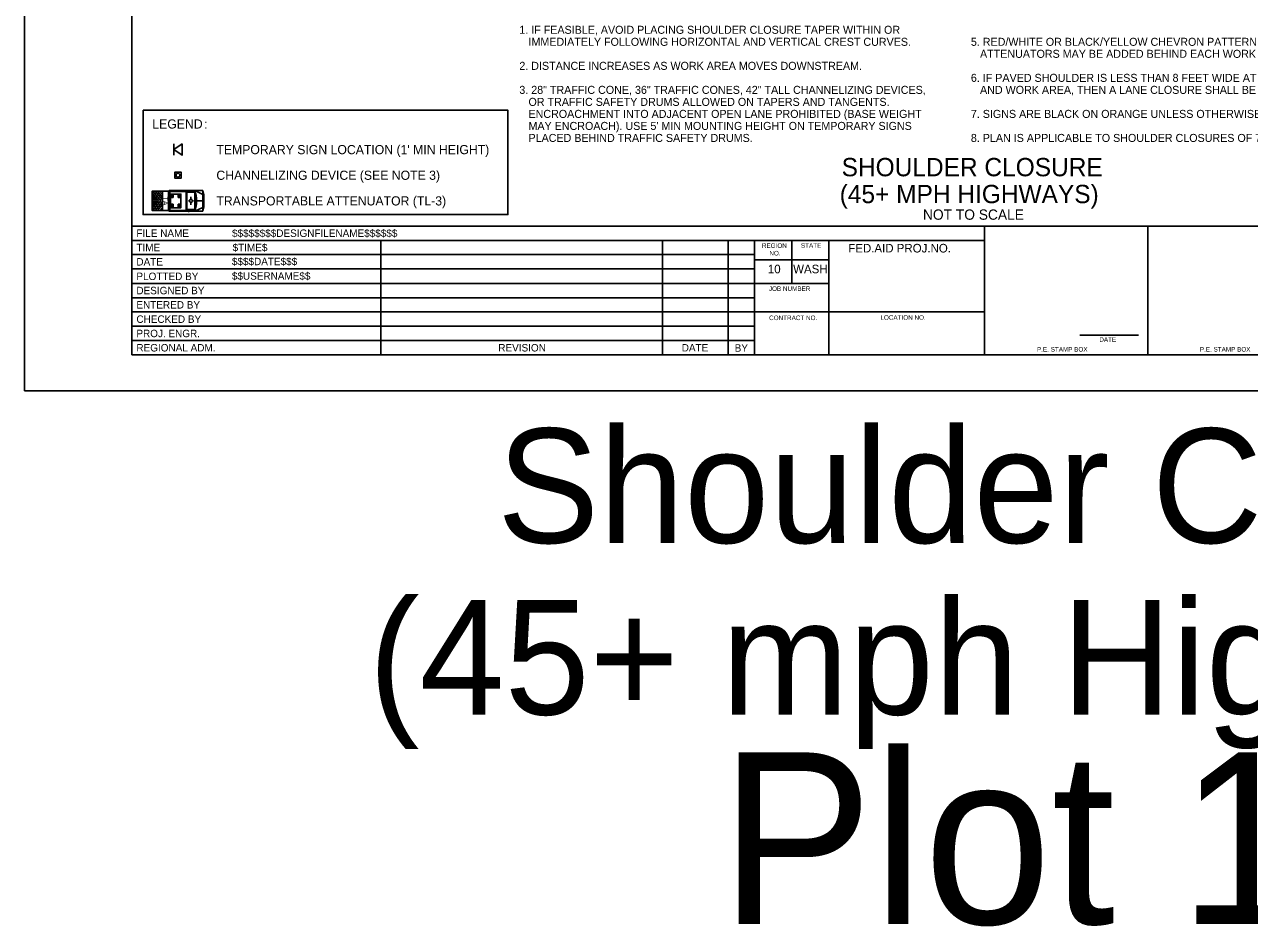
# Model space of a CAD drawing. Extents: x 99999.1 to 100055.7, y 99995 to 100013.2.
# Drawn here: x 99999.06 to 100009.77, y 99995.01 to 100002.89 of the extents above; entities that cross this region are included whole.
import ezdxf

# ---------------------------------------------------------------- set-up
doc = ezdxf.new("R2010")
doc.units = 0
for name, color, linetype in [('SH_DE_DetailHeading1Text', 7, 'Continuous'), ('SH_GI_GeneralNotesBodyText', 7, 'Continuous'), ('SH_GI_PlotLimits', 7, 'Continuous'), ('SH_GI_SheetBorder', 7, 'Continuous'), ('SH_GI_SheetLocationText', 7, 'Continuous'), ('SH_GI_SheetTextInCells', 7, 'Continuous'), ('SH_GI_TitleBlockText', 7, 'Continuous'), ('TR_WZ_PortableSignMountBlk-Wht', 7, 'Continuous'), ('TR_WZ_TrafficCone', 7, 'Continuous'), ('TR_WZ_TransportableAttenuator', 7, 'Continuous'), ('TR_WZ_WorkZoneTextCurrent', 7, 'Continuous')]:
    doc.layers.add(name, color=color, linetype=linetype)

msp = doc.modelspace()

# ---------------------------------------------------------------- linework, layer by layer
at = {"layer": 'SH_GI_PlotLimits'}
msp.add_lwpolyline([(99999.062, 99999.687), (100016.062, 99999.687), (100016.062, 100010.687), (99999.062, 100010.687)], close=True, dxfattribs=at)
at = {"layer": 'SH_GI_SheetBorder'}
for p, q in [((100000, 100010.375), (100000, 100000)), ((100000, 100001.126), (100015.75, 100001.126)), ((100007.457, 100000), (100007.457, 100001.126)), ((100008.883, 100000), (100008.883, 100001.126)), ((100000, 100001.001), (100007.457, 100001.001)), ((100002.179, 100001.001), (100002.179, 100000)), ((100004.641, 100001.001), (100004.641, 100000)), ((100005.216, 100001.001), (100005.216, 100000)), ((100005.445, 100001.001), (100005.445, 100000)), ((100005.772, 100000.625), (100005.772, 100001.001)), ((100006.096, 100000), (100006.096, 100001.001)), ((100000, 100000.876), (100002.182, 100000.876)), ((100002.182, 100000.876), (100005.447, 100000.876)), ((100006.096, 100000.831), (100005.447, 100000.831)), ((100000, 100000.751), (100002.182, 100000.751)), ((100002.182, 100000.751), (100005.447, 100000.751)), ((100000, 100000.625), (100005.447, 100000.625)), ((100006.096, 100000.625), (100005.447, 100000.625)), ((100000, 100000.5), (100005.447, 100000.5)), ((100000, 100000.375), (100005.447, 100000.375)), ((100007.457, 100000.375), (100005.447, 100000.375)), ((100000, 100000.25), (100005.447, 100000.25)), ((100008.29, 100000.173), (100008.802, 100000.173)), ((100000, 100000.125), (100005.447, 100000.125)), ((100000, 100000), (100015.75, 100000))]:
    msp.add_line(p, q, dxfattribs=at)
at = {"layer": 'TR_WZ_PortableSignMountBlk-Wht'}
msp.add_line((100000.368, 100001.744), (100000.368, 100001.844), dxfattribs=at)
msp.add_lwpolyline([(100000.368, 100001.794), (100000.44, 100001.844), (100000.44, 100001.744)], close=True, dxfattribs=at)
at = {"layer": 'TR_WZ_TrafficCone'}
for points in [[(100000.431, 100001.597), (100000.431, 100001.543), (100000.377, 100001.543), (100000.377, 100001.597), (100000.431, 100001.597)], [(100000.377, 100001.597), (100000.377, 100001.543), (100000.431, 100001.543), (100000.431, 100001.597), (100000.377, 100001.597)]]:
    msp.add_lwpolyline(points, dxfattribs=at)
msp.add_circle((100000.404, 100001.57), 0.0167, dxfattribs=at)
at = {"layer": 'TR_WZ_TransportableAttenuator'}
for p, q in [((100000.179, 100001.414), (100000.235, 100001.347)), ((100000.179, 100001.393), (100000.179, 100001.414)), ((100000.235, 100001.347), (100000.179, 100001.414)), ((100000.179, 100001.414), (100000.179, 100001.393)), ((100000.217, 100001.347), (100000.179, 100001.393)), ((100000.179, 100001.393), (100000.217, 100001.347)), ((100000.179, 100001.369), (100000.199, 100001.346)), ((100000.179, 100001.323), (100000.179, 100001.369)), ((100000.199, 100001.346), (100000.179, 100001.369)), ((100000.179, 100001.369), (100000.179, 100001.323)), ((100000.235, 100001.347), (100000.179, 100001.279)), ((100000.179, 100001.301), (100000.217, 100001.347)), ((100000.217, 100001.347), (100000.179, 100001.301)), ((100000.179, 100001.279), (100000.235, 100001.347)), ((100000.199, 100001.346), (100000.179, 100001.323)), ((100000.179, 100001.323), (100000.199, 100001.346)), ((100000.255, 100001.346), (100000.185, 100001.431)), ((100000.185, 100001.431), (100000.204, 100001.431)), ((100000.185, 100001.431), (100000.255, 100001.346)), ((100000.204, 100001.431), (100000.185, 100001.431)), ((100000.185, 100001.261), (100000.255, 100001.346)), ((100000.255, 100001.346), (100000.185, 100001.261)), ((100000.204, 100001.431), (100000.268, 100001.354)), ((100000.268, 100001.354), (100000.204, 100001.431)), ((100000.268, 100001.378), (100000.225, 100001.431)), ((100000.225, 100001.431), (100000.244, 100001.431)), ((100000.244, 100001.431), (100000.225, 100001.431)), ((100000.225, 100001.431), (100000.268, 100001.378)), ((100000.244, 100001.431), (100000.268, 100001.402)), ((100000.268, 100001.402), (100000.244, 100001.431)), ((100000.268, 100001.262), (100000.268, 100001.431)), ((100000.328, 100001.431), (100000.268, 100001.431)), ((100000.268, 100001.402), (100000.268, 100001.378)), ((100000.268, 100001.378), (100000.268, 100001.402)), ((100000.268, 100001.354), (100000.268, 100001.338)), ((100000.268, 100001.338), (100000.268, 100001.354)), ((100000.321, 100001.427), (100000.321, 100001.264)), ((100000.321, 100001.359), (100000.327, 100001.355)), ((100000.323, 100001.346), (100000.326, 100001.346)), ((100000.324, 100001.433), (100000.327, 100001.433)), ((100000.324, 100001.348), (100000.324, 100001.343)), ((100000.327, 100001.433), (100000.327, 100001.259)), ((100000.328, 100001.436), (100000.48, 100001.436)), ((100000.328, 100001.436), (100000.328, 100001.256)), ((100000.328, 100001.43), (100000.328, 100001.262)), ((100000.332, 100001.429), (100000.332, 100001.263)), ((100000.332, 100001.429), (100000.476, 100001.429)), ((100000.476, 100001.429), (100000.476, 100001.263)), ((100000.48, 100001.436), (100000.48, 100001.256)), ((100000.482, 100001.436), (100000.482, 100001.256)), ((100000.622, 100001.436), (100000.482, 100001.436)), ((100000.551, 100001.422), (100000.482, 100001.422)), ((100000.501, 100001.438), (100000.493, 100001.438)), ((100000.495, 100001.346), (100000.504, 100001.346)), ((100000.507, 100001.346), (100000.507, 100001.346)), ((100000.517, 100001.382), (100000.517, 100001.367)), ((100000.54, 100001.346), (100000.53, 100001.346)), ((100000.551, 100001.436), (100000.542, 100001.422)), ((100000.551, 100001.436), (100000.551, 100001.256)), ((100000.552, 100001.436), (100000.552, 100001.256)), ((100000.622, 100001.403), (100000.552, 100001.436)), ((100000.622, 100001.346), (100000.566, 100001.346)), ((100000.622, 100001.436), (100000.622, 100001.256)), ((100000.622, 100001.436), (100000.629, 100001.4)), ((100000.629, 100001.4), (100000.629, 100001.292)), ((100000.179, 100001.279), (100000.179, 100001.301)), ((100000.179, 100001.301), (100000.179, 100001.279)), ((100000.204, 100001.261), (100000.185, 100001.261)), ((100000.185, 100001.261), (100000.204, 100001.261)), ((100000.268, 100001.338), (100000.204, 100001.261)), ((100000.204, 100001.261), (100000.268, 100001.338)), ((100000.224, 100001.261), (100000.268, 100001.314)), ((100000.268, 100001.314), (100000.224, 100001.261)), ((100000.245, 100001.261), (100000.224, 100001.261)), ((100000.224, 100001.261), (100000.245, 100001.261)), ((100000.268, 100001.289), (100000.245, 100001.261)), ((100000.245, 100001.261), (100000.268, 100001.289)), ((100000.268, 100001.314), (100000.268, 100001.289)), ((100000.268, 100001.289), (100000.268, 100001.314)), ((100000.328, 100001.262), (100000.268, 100001.262)), ((100000.321, 100001.333), (100000.327, 100001.337)), ((100000.324, 100001.259), (100000.327, 100001.259)), ((100000.328, 100001.256), (100000.48, 100001.256)), ((100000.332, 100001.263), (100000.476, 100001.263)), ((100000.551, 100001.27), (100000.482, 100001.27)), ((100000.622, 100001.256), (100000.482, 100001.256)), ((100000.501, 100001.253), (100000.493, 100001.253)), ((100000.517, 100001.31), (100000.517, 100001.325)), ((100000.544, 100001.27), (100000.551, 100001.256)), ((100000.622, 100001.289), (100000.552, 100001.256)), ((100000.622, 100001.256), (100000.629, 100001.292))]:
    msp.add_line(p, q, dxfattribs=at)
for points in [[(100000.268, 100001.261), (100000.179, 100001.261), (100000.179, 100001.431), (100000.268, 100001.431)], [(100000.34, 100001.406), (100000.43, 100001.406), (100000.43, 100001.286), (100000.34, 100001.286)], [(100000.347, 100001.398), (100000.362, 100001.398), (100000.362, 100001.376), (100000.347, 100001.376)], [(100000.422, 100001.398), (100000.407, 100001.398), (100000.407, 100001.376), (100000.422, 100001.376)], [(100000.347, 100001.316), (100000.362, 100001.316), (100000.362, 100001.293), (100000.347, 100001.293)], [(100000.422, 100001.316), (100000.407, 100001.316), (100000.407, 100001.293), (100000.422, 100001.293)]]:
    msp.add_lwpolyline(points, close=True, dxfattribs=at)
msp.add_lwpolyline([(100000.268, 100001.431), (100000.179, 100001.431), (100000.179, 100001.261), (100000.268, 100001.262)], dxfattribs=at)
for centre, major_axis, start_param, end_param in [((100000.324, 100001.427), (0, 0.00549), 6.283185, 7.853982), ((100000.452, 100001.346), (0, 0.189), 4.215852, 5.209111), ((100000.324, 100001.264), (0, -0.00549), 4.712389, 6.283185)]:
    msp.add_ellipse(centre, major_axis=major_axis, ratio=0.60201, start_param=start_param, end_param=end_param, dxfattribs=at)
for centre, major_axis in [((100000.324, 100001.346), (0, -0.00254)), ((100000.517, 100001.346), (0, -0.0173))]:
    msp.add_ellipse(centre, major_axis=major_axis, ratio=0.60201, dxfattribs=at)
at = {"layer": 'TR_WZ_WorkZoneTextCurrent'}
msp.add_lwpolyline([(100000.1, 100002.138), (100003.289, 100002.138), (100003.289, 100001.226), (100000.1, 100001.226)], close=True, dxfattribs=at)

# ---------------------------------------------------------------- texts
at = {"layer": 'SH_DE_DetailHeading1Text'}
for s, height, p in [('SHOULDER CLOSURE', 0.16, (100006.207, 100001.561)), ('(45+ MPH HIGHWAYS)', 0.16, (100006.19, 100001.326)), ('NOT TO SCALE', 0.09, (100006.918, 100001.181))]:
    msp.add_text(s, height=height, rotation=360, dxfattribs=at).set_placement(p)
at = {"layer": 'SH_GI_GeneralNotesBodyText'}
for s, p in [('1. IF FEASIBLE, AVOID PLACING SHOULDER CLOSURE TAPER WITHIN OR ', (100003.389, 100002.806)), ('IMMEDIATELY FOLLOWING HORIZONTAL AND VERTICAL CREST CURVES.', (100003.469, 100002.701)), ('5. RED/WHITE OR BLACK/YELLOW CHEVRON PATTERN OK. ADDITIONAL TRANSPORTABLE ', (100007.337, 100002.701)), ('ATTENUATORS MAY BE ADDED BEHIND EACH WORK CREW.', (100007.417, 100002.596)), ('2. DISTANCE INCREASES AS WORK AREA MOVES DOWNSTREAM.', (100003.389, 100002.491)), ('6. IF PAVED SHOULDER IS LESS THAN 8 FEET WIDE AT TRANSPORTABLE ATTENUATORS ', (100007.337, 100002.386)), ('3. 28" TRAFFIC CONE, 36" TRAFFIC CONES, 42" TALL CHANNELIZING DEVICES, ', (100003.389, 100002.281)), ('AND WORK AREA, THEN A LANE CLOSURE SHALL BE IMPLEMENTED.', (100007.417, 100002.281)), ('OR TRAFFIC SAFETY DRUMS ALLOWED ON TAPERS AND TANGENTS.  ', (100003.469, 100002.176)), ('ENCROACHMENT INTO ADJACENT OPEN LANE PROHIBITED (BASE WEIGHT ', (100003.469, 100002.071)), ('7. SIGNS ARE BLACK ON ORANGE UNLESS OTHERWISE INDICATED.', (100007.337, 100002.071)), ("MAY ENCROACH). USE 5' MIN MOUNTING HEIGHT ON TEMPORARY SIGNS ", (100003.469, 100001.966)), ('PLACED BEHIND TRAFFIC SAFETY DRUMS.', (100003.469, 100001.861)), ('8. PLAN IS APPLICABLE TO SHOULDER CLOSURES OF 7 DAYS OR LESS.', (100007.337, 100001.861))]:
    msp.add_text(s, height=0.07, rotation=360, dxfattribs=at).set_placement(p)
at = {"layer": 'SH_GI_SheetLocationText'}
for s, height, p in [('Shoulder Closure', 1, (100003.195, 99998.357)), ('(45+ mph Highways)', 1, (100002.071, 99996.857)), ('Plot 1', 1.5, (100005.142, 99995.027))]:
    msp.add_text(s, height=height, dxfattribs=at).set_placement(p)
at = {"layer": 'SH_GI_SheetTextInCells'}
for s, height, p in [('FILE NAME', 0.0651, (100000.041, 100001.031)), ('TIME', 0.0651, (100000.041, 100000.906)), ('REGION', 0.04, (100005.51, 100000.935)), ('STATE', 0.04, (100005.851, 100000.936)), ('FED.AID PROJ.NO.', 0.07506, (100006.265, 100000.895)), ('DATE', 0.0651, (100000.041, 100000.781)), ('NO.', 0.04, (100005.575, 100000.869)), ('PLOTTED BY', 0.0651, (100000.041, 100000.654)), ('10', 0.0751, (100005.562, 100000.713)), ('WASH', 0.0751, (100005.783, 100000.713)), ('DESIGNED BY', 0.06505, (100000.041, 100000.53)), ('JOB NUMBER', 0.04, (100005.571, 100000.559)), ('ENTERED BY', 0.0651, (100000.041, 100000.405)), ('CHECKED BY', 0.0651, (100000.041, 100000.28)), ('CONTRACT NO.', 0.04003, (100005.573, 100000.304)), ('LOCATION NO.', 0.04003, (100006.546, 100000.307)), ('PROJ. ENGR.', 0.06505, (100000.041, 100000.155)), ('REGIONAL ADM.', 0.06505, (100000.041, 100000.03)), ('REVISION', 0.0651, (100003.205, 100000.03)), ('DATE', 0.0651, (100004.809, 100000.03)), ('BY', 0.0651, (100005.272, 100000.028)), ('P.E. STAMP BOX', 0.04003, (100007.915, 100000.029)), ('DATE', 0.04, (100008.46, 100000.114)), ('P.E. STAMP BOX', 0.04003, (100009.339, 100000.029))]:
    msp.add_text(s, height=height, dxfattribs=at).set_placement(p)
at = {"layer": 'SH_GI_TitleBlockText'}
for s, height, p in [('$$$$$$$$DESIGNFILENAME$$$$$$', 0.06505, (100000.877, 100001.031)), ('$TIME$', 0.0651, (100000.882, 100000.906)), ('$$$$DATE$$$', 0.06505, (100000.876, 100000.784)), ('$$USERNAME$$', 0.06505, (100000.876, 100000.657))]:
    msp.add_text(s, height=height, dxfattribs=at).set_placement(p)
at = {"layer": 'TR_WZ_TransportableAttenuator'}
msp.add_text('TA', height=0.045, rotation=270, dxfattribs=at).set_placement((100000.272, 100001.385))
at = {"layer": 'TR_WZ_WorkZoneTextCurrent'}
for s, p in [('LEGEND', (100000.18, 100001.978)), (':', (100000.633, 100001.978)), ("TEMPORARY SIGN LOCATION (1' MIN HEIGHT)", (100000.74, 100001.754)), ('CHANNELIZING DEVICE (SEE NOTE 3)', (100000.74, 100001.53)), ('TRANSPORTABLE ATTENUATOR (TL-3)', (100000.74, 100001.306))]:
    msp.add_text(s, height=0.08, rotation=360, dxfattribs=at).set_placement(p)

doc.saveas('drawing.dxf')
